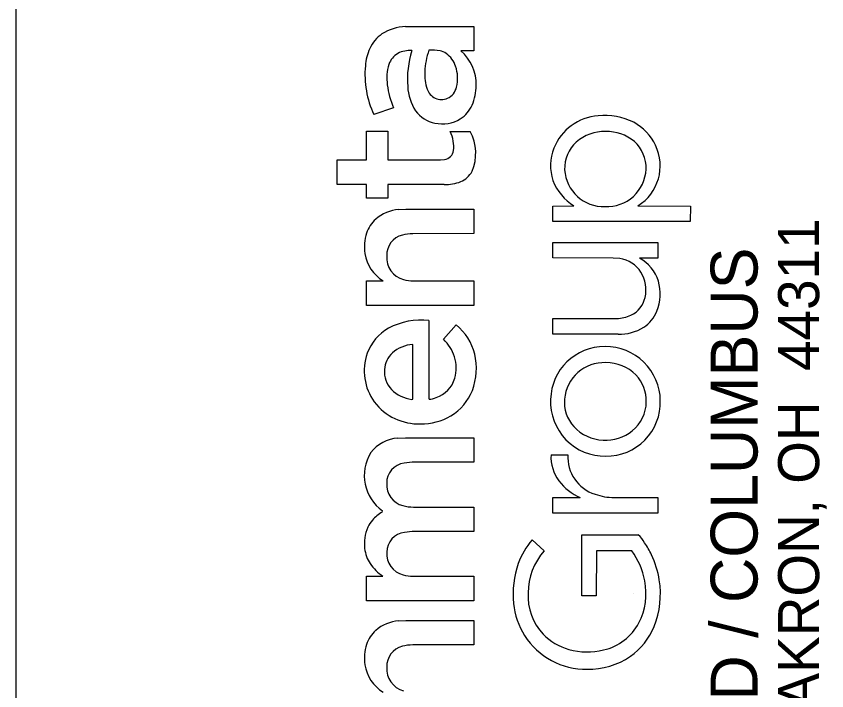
# Model space of a CAD drawing. Extents: x 0 to 34, y 0 to 22.
# Drawn here: x 32 to 32.984, y 3.382 to 4.202 of the extents above; entities that cross this region are included whole.
import ezdxf

# ---------------------------------------------------------------- set-up
doc = ezdxf.new("R2010")
doc.units = 0
doc.layers.add('SH_Border', color=7, linetype='Continuous')
doc.layers.add('SH_Data', color=7, linetype='Continuous')

msp = doc.modelspace()

# ---------------------------------------------------------------- linework, layer by layer
at = {"layer": 'SH_Border'}
msp.add_line((32, 0.5), (32, 21.5), dxfattribs=at)
at = {"layer": 'SH_Data'}
for p, q in [((32.47265, 4.18899), (32.55553, 4.18918)), ((32.55553, 4.18918), (32.55571, 4.15956)), ((32.55571, 4.15956), (32.53971, 4.15956)), ((32.45818, 4.09045), (32.43431, 4.08233)), ((32.42542, 4.02705), (32.42548, 4.06209)), ((32.42548, 4.06209), (32.45108, 4.06209)), ((32.45108, 4.06209), (32.45117, 4.02705)), ((32.52695, 4.06159), (32.5511, 4.06159)), ((32.38964, 4.02701), (32.42542, 4.02705)), ((32.38964, 3.99719), (32.38964, 4.02701)), ((32.45117, 4.02705), (32.51498, 4.02705)), ((32.51498, 4.02705), (32.52005, 4.02749)), ((32.42542, 3.99717), (32.38964, 3.99719)), ((32.42542, 3.98067), (32.42542, 3.99717)), ((32.51969, 3.99718), (32.45108, 3.99715)), ((32.45108, 3.99715), (32.45108, 3.98066)), ((32.45108, 3.98066), (32.42542, 3.98067)), ((32.46439, 3.96686), (32.47289, 3.96732)), ((32.47289, 3.96732), (32.55571, 3.96732)), ((32.55571, 3.96732), (32.55571, 3.93753)), ((32.65152, 3.97113), (32.67709, 3.97115)), ((32.65152, 3.95215), (32.65152, 3.97113)), ((32.75491, 3.97132), (32.81858, 3.97108)), ((32.81858, 3.97108), (32.81843, 3.95215)), ((32.81843, 3.95215), (32.65152, 3.95215)), ((32.55571, 3.93753), (32.4814, 3.93746)), ((32.65152, 3.90801), (32.65153, 3.92672)), ((32.65153, 3.92672), (32.7791, 3.92664)), ((32.7791, 3.92664), (32.77908, 3.90796)), ((32.7249, 3.90796), (32.65152, 3.90801)), ((32.7328, 3.90727), (32.7249, 3.90796)), ((32.77908, 3.90796), (32.75689, 3.90796)), ((32.42542, 3.88016), (32.44552, 3.88021)), ((32.42542, 3.85035), (32.42542, 3.88016)), ((32.48222, 3.88021), (32.55569, 3.88021)), ((32.55569, 3.88021), (32.55571, 3.85045)), ((32.55571, 3.85045), (32.42542, 3.85035)), ((32.50108, 3.83209), (32.50118, 3.73657)), ((32.65154, 3.83443), (32.72905, 3.8345)), ((32.65165, 3.81543), (32.65154, 3.83443)), ((32.51882, 3.80927), (32.53422, 3.82662)), ((32.73073, 3.81543), (32.65165, 3.81543)), ((32.48144, 3.73644), (32.48144, 3.80296)), ((32.48016, 3.73628), (32.48144, 3.73644)), ((32.46329, 3.68915), (32.47259, 3.68968)), ((32.47259, 3.68968), (32.55557, 3.68968)), ((32.55557, 3.68968), (32.55571, 3.65982)), ((32.64932, 3.66907), (32.66978, 3.66907)), ((32.48058, 3.65981), (32.47102, 3.65881)), ((32.55571, 3.65982), (32.48058, 3.65981)), ((32.65152, 3.61699), (32.68476, 3.617)), ((32.65152, 3.598), (32.65152, 3.61699)), ((32.72605, 3.61703), (32.7791, 3.61696)), ((32.7791, 3.61696), (32.77903, 3.598)), ((32.48218, 3.60553), (32.55571, 3.60548)), ((32.55571, 3.60548), (32.55571, 3.57568)), ((32.44443, 3.59922), (32.44455, 3.60072)), ((32.77903, 3.598), (32.65152, 3.598)), ((32.4809, 3.57567), (32.47143, 3.57474)), ((32.55571, 3.57568), (32.4809, 3.57567)), ((32.62636, 3.56548), (32.64114, 3.55241)), ((32.6868, 3.57185), (32.75516, 3.57192)), ((32.6868, 3.49778), (32.6868, 3.57185)), ((32.70448, 3.55241), (32.70432, 3.49775)), ((32.74737, 3.55227), (32.70448, 3.55241)), ((32.42542, 3.49152), (32.42545, 3.52138)), ((32.42545, 3.52138), (32.44515, 3.52138)), ((32.48206, 3.52138), (32.55571, 3.52136)), ((32.55571, 3.52136), (32.55571, 3.49156)), ((32.70432, 3.49775), (32.6868, 3.49778)), ((32.75, 3.5), (32.75, 3.5)), ((32.55571, 3.49156), (32.42542, 3.49152)), ((32.46439, 3.46736), (32.47289, 3.46783)), ((32.47289, 3.46783), (32.55571, 3.46783)), ((32.55571, 3.46783), (32.55571, 3.43804)), ((32.55571, 3.43804), (32.4814, 3.43796))]:
    msp.add_line(p, q, dxfattribs=at)
for points in [[(32.47265, 4.18899), (32.55553, 4.18918), (32.55571, 4.15956)], [(32.55571, 4.15956), (32.53971, 4.15956)], [(32.45818, 4.09045), (32.43431, 4.08233)], [(32.51969, 3.99718), (32.45108, 3.99715), (32.45108, 3.98066), (32.42542, 3.98067), (32.42542, 3.99717), (32.38964, 3.99719), (32.38964, 4.02701), (32.42542, 4.02705), (32.42548, 4.06209), (32.45108, 4.06209), (32.45117, 4.02705), (32.51498, 4.02705), (32.52005, 4.02749)], [(32.52695, 4.06159), (32.5511, 4.06159)], [(32.46439, 3.96686), (32.47289, 3.96732), (32.55571, 3.96732), (32.55571, 3.93753), (32.4814, 3.93746)], [(32.75491, 3.97132), (32.81858, 3.97108), (32.81843, 3.95215), (32.65152, 3.95215)], [(32.65152, 3.95215), (32.65152, 3.97113), (32.67709, 3.97115)], [(32.7328, 3.90727), (32.7249, 3.90796), (32.65152, 3.90801), (32.65153, 3.92672), (32.7791, 3.92664), (32.77908, 3.90796), (32.75689, 3.90796)], [(32.42542, 3.85035), (32.42542, 3.88016), (32.44552, 3.88021)], [(32.48222, 3.88021), (32.55569, 3.88021), (32.55571, 3.85045), (32.42542, 3.85035)], [(32.50108, 3.83209), (32.50118, 3.73657)], [(32.73073, 3.81543), (32.65165, 3.81543), (32.65154, 3.83443), (32.72905, 3.8345)], [(32.51882, 3.80927), (32.53422, 3.82662)], [(32.48016, 3.73628), (32.48144, 3.73644), (32.48144, 3.80296)], [(32.46329, 3.68915), (32.47259, 3.68968), (32.55557, 3.68968), (32.55571, 3.65982), (32.48058, 3.65981), (32.47102, 3.65881)], [(32.64932, 3.66907), (32.66978, 3.66907)], [(32.72605, 3.61703), (32.7791, 3.61696), (32.77903, 3.598), (32.65152, 3.598)], [(32.65152, 3.598), (32.65152, 3.61699), (32.68476, 3.617)], [(32.48218, 3.60553), (32.55571, 3.60548), (32.55571, 3.57568), (32.4809, 3.57567), (32.47143, 3.57474)], [(32.44443, 3.59922), (32.44455, 3.60072)], [(32.62636, 3.56548), (32.64114, 3.55241)], [(32.74737, 3.55227), (32.70448, 3.55241), (32.70432, 3.49775), (32.6868, 3.49778), (32.6868, 3.57185), (32.75516, 3.57192)], [(32.42542, 3.49152), (32.42545, 3.52138), (32.44515, 3.52138)], [(32.48206, 3.52138), (32.55571, 3.52136), (32.55571, 3.49156), (32.42542, 3.49152)], [(32.46439, 3.46736), (32.47289, 3.46783), (32.55571, 3.46783), (32.55571, 3.43804), (32.4814, 3.43796)]]:
    msp.add_lwpolyline(points, dxfattribs=at)
for centre, radius, start, end in [((32.47452, 4.13256), 0.05646, 91.89422, 122.63175), ((32.47452, 4.13256), 0.05646, 91.89422, 122.63175), ((32.46847, 4.14467), 0.04302, 124.53704, 155.65938), ((32.46847, 4.14467), 0.04302, 124.53704, 155.65938), ((32.48824, 4.13612), 0.06457, 155.9764, 175.31491), ((32.48824, 4.13612), 0.06457, 155.9764, 175.31491), ((32.47525, 4.1356), 0.024, 119.42515, 161.66285), ((32.47525, 4.1356), 0.024, 119.42515, 161.66285), ((32.47786, 4.12778), 0.03213, 85.38017, 116.62224), ((32.47786, 4.12778), 0.03213, 85.38017, 116.62224), ((32.58787, 4.12508), 0.1129, 162.08213, 184.52847), ((32.58787, 4.12508), 0.1129, 162.08213, 184.52847), ((32.58013, 4.13131), 0.08411, 159.83657, 178.03621), ((32.58013, 4.13131), 0.08411, 159.83657, 178.03621), ((32.50509, 4.10743), 0.05302, 79.66963, 94.23216), ((32.50509, 4.10743), 0.05302, 79.66963, 94.23216), ((32.50892, 4.13643), 0.02384, 56.89129, 76.21489), ((32.50892, 4.13643), 0.02384, 56.89129, 76.21489), ((32.5052, 4.13184), 0.02973, 17.59837, 55.72819), ((32.5052, 4.13184), 0.02973, 17.59837, 55.72819), ((32.50551, 4.11914), 0.05295, 358.07459, 49.76196), ((32.50551, 4.11914), 0.05295, 358.07459, 49.76196), ((32.53639, 4.13078), 0.113, 174.61011, 205.38987), ((32.53639, 4.13078), 0.113, 174.61011, 205.38987), ((32.50758, 4.12645), 0.05758, 163.13694, 188.16749), ((32.50758, 4.12645), 0.05758, 163.13694, 188.16749), ((32.54655, 4.1303), 0.05063, 175.59026, 199.88569), ((32.54655, 4.1303), 0.05063, 175.59026, 199.88569), ((32.4916, 4.1264), 0.04435, 345.94084, 18.99188), ((32.4916, 4.1264), 0.04435, 345.94084, 18.99188), ((32.54725, 4.12973), 0.09735, 186.75982, 203.79807), ((32.54725, 4.12973), 0.09735, 186.75982, 203.79807), ((32.53279, 4.11874), 0.05752, 182.56764, 213.71437), ((32.53279, 4.11874), 0.05752, 182.56764, 213.71437), ((32.51521, 4.11994), 0.01989, 295.28829, 347.46387), ((32.51521, 4.11994), 0.01989, 295.28829, 347.46387), ((32.50187, 4.11678), 0.05657, 336.01604, 0.59505), ((32.50187, 4.11678), 0.05657, 336.01604, 0.59505), ((32.51642, 4.11886), 0.01841, 198.28436, 293.30806), ((32.51642, 4.11886), 0.01841, 198.28436, 293.30806), ((32.51487, 4.10782), 0.03656, 215.06685, 259.81327), ((32.51487, 4.10782), 0.03656, 215.06685, 259.81327), ((32.51752, 4.10969), 0.03938, 303.44357, 336.18), ((32.51752, 4.10969), 0.03938, 303.44357, 336.18), ((32.51753, 4.1131), 0.04227, 257.52557, 300.88195), ((32.51753, 4.1131), 0.04227, 257.52557, 300.88195), ((32.71081, 4.01825), 0.06243, 93.98662, 158.31194), ((32.71081, 4.01825), 0.06243, 93.98662, 158.31194), ((32.71557, 4.0065), 0.07459, 62.68889, 97.01346), ((32.71557, 4.0065), 0.07459, 62.68889, 97.01346), ((32.72123, 4.01914), 0.06076, 25.06574, 61.96022), ((32.72123, 4.01914), 0.06076, 25.06574, 61.96022), ((32.48625, 4.04199), 0.04518, 10.15449, 25.72303), ((32.48625, 4.04199), 0.04518, 10.15449, 25.72303), ((32.50302, 4.03506), 0.05491, 336.58903, 28.89913), ((32.50302, 4.03506), 0.05491, 336.58903, 28.89913), ((32.71379, 4.01017), 0.05134, 87.89653, 131.18123), ((32.71379, 4.01017), 0.05134, 87.89653, 131.18123), ((32.7175, 4.01023), 0.05127, 49.90886, 92.03625), ((32.7175, 4.01023), 0.05127, 49.90886, 92.03625), ((32.49573, 4.04365), 0.03556, 351.91398, 10.20594), ((32.49573, 4.04365), 0.03556, 351.91398, 10.20594), ((32.7092, 4.01674), 0.04338, 132.32887, 182.09489), ((32.7092, 4.01674), 0.04338, 132.32887, 182.09489), ((32.72154, 4.01733), 0.04327, 358.04871, 47.94467), ((32.72154, 4.01733), 0.04327, 358.04871, 47.94467), ((32.7245, 4.02004), 0.05743, 301.97764, 25.64176), ((32.7245, 4.02004), 0.05743, 301.97764, 25.64176), ((32.51837, 4.04001), 0.01263, 277.61423, 353.79181), ((32.51837, 4.04001), 0.01263, 277.61423, 353.79181), ((32.70695, 4.02016), 0.05815, 158.65601, 198.17101), ((32.70695, 4.02016), 0.05815, 158.65601, 198.17101), ((32.71717, 4.01801), 0.04766, 267.31494, 357.4019), ((32.71717, 4.01801), 0.04766, 267.31494, 357.4019), ((32.52913, 4.02612), 0.02749, 292.68889, 332.05977), ((32.52913, 4.02612), 0.02749, 292.68889, 332.05977), ((32.71352, 4.01815), 0.04776, 183.59741, 271.7045), ((32.71352, 4.01815), 0.04776, 183.59741, 271.7045), ((32.52088, 4.04856), 0.05139, 268.67266, 291.52354), ((32.52088, 4.04856), 0.05139, 268.67266, 291.52354), ((32.7103, 4.02433), 0.0627, 200.83985, 238.01619), ((32.7103, 4.02433), 0.0627, 200.83985, 238.01619), ((32.46871, 3.91716), 0.04988, 94.97056, 130.22484), ((32.46871, 3.91716), 0.04988, 94.97056, 130.22484), ((32.46348, 3.92551), 0.04016, 132.22383, 161.68229), ((32.46348, 3.92551), 0.04016, 132.22383, 161.68229), ((32.47872, 3.92108), 0.05602, 162.27398, 187.79173), ((32.47872, 3.92108), 0.05602, 162.27398, 187.79173), ((32.48108, 3.89145), 0.04601, 89.60515, 105.33026), ((32.48108, 3.89145), 0.04601, 89.60515, 105.33026), ((32.47482, 3.91155), 0.02498, 103.68683, 182.21395), ((32.47482, 3.91155), 0.02498, 103.68683, 182.21395), ((32.47027, 3.9209), 0.04763, 188.96462, 238.69865), ((32.47027, 3.9209), 0.04763, 188.96462, 238.69865), ((32.47735, 3.90846), 0.02757, 175.58441, 255.13816), ((32.47735, 3.90846), 0.02757, 175.58441, 255.13816), ((32.72711, 3.86998), 0.03772, 33.50082, 81.32954), ((32.72711, 3.86998), 0.03772, 33.50082, 81.32954), ((32.73239, 3.86485), 0.04959, 17.62209, 60.38974), ((32.73239, 3.86485), 0.04959, 17.62209, 60.38974), ((32.72414, 3.8695), 0.04048, 346.56179, 31.75389), ((32.72414, 3.8695), 0.04048, 346.56179, 31.75389), ((32.48183, 3.92235), 0.04215, 254.08913, 270.52838), ((32.48183, 3.92235), 0.04215, 254.08913, 270.52838), ((32.72343, 3.86415), 0.05838, 339.16197, 15.61485), ((32.72343, 3.86415), 0.05838, 339.16197, 15.61485), ((32.73371, 3.86616), 0.03042, 294.63214, 348.48625), ((32.73371, 3.86616), 0.03042, 294.63214, 348.48625), ((32.72747, 3.88081), 0.04633, 271.95199, 294.08943), ((32.72747, 3.88081), 0.04633, 271.95199, 294.08943), ((32.739, 3.85901), 0.04201, 303.10391, 338.15613), ((32.739, 3.85901), 0.04201, 303.10391, 338.15613), ((32.49176, 3.74874), 0.08387, 83.62118, 118.28448), ((32.49176, 3.74874), 0.08387, 83.62118, 118.28448), ((32.47894, 3.77368), 0.05583, 118.82935, 160.62242), ((32.47894, 3.77368), 0.05583, 118.82935, 160.62242), ((32.49399, 3.7763), 0.06443, 13.53275, 51.36266), ((32.49399, 3.7763), 0.06443, 13.53275, 51.36266), ((32.7321, 3.87256), 0.05715, 268.62699, 301.47779), ((32.7321, 3.87256), 0.05715, 268.62699, 301.47779), ((32.48033, 3.77018), 0.05485, 19.0387, 45.44322), ((32.48033, 3.77018), 0.05485, 19.0387, 45.44322), ((32.4844, 3.76071), 0.04236, 94.01311, 130.88062), ((32.4844, 3.76071), 0.04236, 94.01311, 130.88062), ((32.71435, 3.73484), 0.06552, 89.48213, 178.77752), ((32.71435, 3.73484), 0.06552, 89.48213, 178.77752), ((32.71582, 3.73414), 0.06623, 0.42265, 90.7613), ((32.71582, 3.73414), 0.06623, 0.42265, 90.7613), ((32.48697, 3.77074), 0.06438, 160.52138, 215.78155), ((32.48697, 3.77074), 0.06438, 160.52138, 215.78155), ((32.47703, 3.7709), 0.02985, 132.98553, 177.1802), ((32.47703, 3.7709), 0.02985, 132.98553, 177.1802), ((32.48289, 3.77384), 0.0758, 339.35431, 13.37708), ((32.48289, 3.77384), 0.0758, 339.35431, 13.37708), ((32.48724, 3.77433), 0.04701, 344.60723, 17.00675), ((32.48724, 3.77433), 0.04701, 344.60723, 17.00675), ((32.71397, 3.73244), 0.04846, 87.68827, 175.01696), ((32.71397, 3.73244), 0.04846, 87.68827, 175.01696), ((32.71659, 3.73036), 0.05052, 44.91202, 90.75914), ((32.71659, 3.73036), 0.05052, 44.91202, 90.75914), ((32.47824, 3.76966), 0.03114, 175.00138, 223.2876), ((32.47824, 3.76966), 0.03114, 175.00138, 223.2876), ((32.49895, 3.77177), 0.03504, 288.01084, 343.55364), ((32.49895, 3.77177), 0.03504, 288.01084, 343.55364), ((32.71955, 3.73452), 0.04549, 358.32279, 43.83486), ((32.71955, 3.73452), 0.04549, 358.32279, 43.83486), ((32.48546, 3.77826), 0.04232, 225.06454, 262.79701), ((32.48546, 3.77826), 0.04232, 225.06454, 262.79701), ((32.49548, 3.76982), 0.0626, 300.94393, 338.73223), ((32.49548, 3.76982), 0.0626, 300.94393, 338.73223), ((32.48908, 3.77516), 0.06872, 217.74341, 271.65606), ((32.48908, 3.77516), 0.06872, 217.74341, 271.65606), ((32.50129, 3.75678), 0.02021, 269.70042, 294.87295), ((32.50129, 3.75678), 0.02021, 269.70042, 294.87295), ((32.71483, 3.7334), 0.06606, 177.53728, 270.94524), ((32.71483, 3.7334), 0.06606, 177.53728, 270.94524), ((32.71085, 3.73311), 0.0453, 175.51467, 221.42047), ((32.71085, 3.73311), 0.0453, 175.51467, 221.42047), ((32.71671, 3.73271), 0.06536, 269.30834, 1.67905), ((32.71671, 3.73271), 0.06536, 269.30834, 1.67905), ((32.71931, 3.73374), 0.04572, 308.90382, 359.30947), ((32.71931, 3.73374), 0.04572, 308.90382, 359.30947), ((32.49204, 3.77702), 0.07055, 269.20529, 300.33566), ((32.49204, 3.77702), 0.07055, 269.20529, 300.33566), ((32.71399, 3.73734), 0.05046, 222.66255, 268.37331), ((32.71399, 3.73734), 0.05046, 222.66255, 268.37331), ((32.71567, 3.73859), 0.05178, 266.55312, 308.67253), ((32.71567, 3.73859), 0.05178, 266.55312, 308.67253), ((32.46638, 3.64404), 0.04521, 93.91118, 142.30723), ((32.46638, 3.64404), 0.04521, 93.91118, 142.30723), ((32.47585, 3.64373), 0.05319, 148.28793, 233.9556), ((32.47585, 3.64373), 0.05319, 148.28793, 233.9556), ((32.69878, 3.66662), 0.04952, 177.16211, 216.28024), ((32.69878, 3.66662), 0.04952, 177.16211, 216.28024), ((32.71735, 3.66638), 0.04764, 176.76988, 252.15044), ((32.71735, 3.66638), 0.04764, 176.76988, 252.15044), ((32.47384, 3.63499), 0.02399, 96.75763, 181.6251), ((32.47384, 3.63499), 0.02399, 96.75763, 181.6251), ((32.47577, 3.63241), 0.02597, 175.81573, 256.16716), ((32.47577, 3.63241), 0.02597, 175.81573, 256.16716), ((32.70975, 3.67555), 0.06366, 216.91526, 246.88619), ((32.70975, 3.67555), 0.06366, 216.91526, 246.88619), ((32.7269, 3.69175), 0.07473, 251.13884, 269.34694), ((32.7269, 3.69175), 0.07473, 251.13884, 269.34694), ((32.4817, 3.65053), 0.04501, 254.34629, 270.61033), ((32.4817, 3.65053), 0.04501, 254.34629, 270.61033), ((32.4638, 3.56267), 0.04137, 117.91625, 139.24296), ((32.4638, 3.56267), 0.04137, 117.91625, 139.24296), ((32.46194, 3.56452), 0.03875, 139.52447, 154.84698), ((32.46194, 3.56452), 0.03875, 139.52447, 154.84698), ((32.47144, 3.5612), 0.04877, 156.06382, 187.3493), ((32.47144, 3.5612), 0.04877, 156.06382, 187.3493), ((32.47421, 3.55056), 0.02434, 96.5532, 179.94902), ((32.47421, 3.55056), 0.02434, 96.5532, 179.94902), ((32.70163, 3.50187), 0.09855, 139.79476, 159.13696), ((32.70163, 3.50187), 0.09855, 139.79476, 159.13696), ((32.72498, 3.53937), 0.04438, 30.98913, 47.16099), ((32.72498, 3.53937), 0.04438, 30.98913, 47.16099), ((32.46461, 3.55974), 0.04181, 186.5579, 213.38846), ((32.46461, 3.55974), 0.04181, 186.5579, 213.38846), ((32.67091, 3.50018), 0.11106, 25.30315, 33.96179), ((32.67091, 3.50018), 0.11106, 25.30315, 33.96179), ((32.47608, 3.54863), 0.02628, 175.722, 255.78627), ((32.47608, 3.54863), 0.02628, 175.722, 255.78627), ((32.69899, 3.50079), 0.07753, 138.25804, 179.70064), ((32.69899, 3.50079), 0.07753, 138.25804, 179.70064), ((32.67889, 3.50099), 0.08556, 10.07509, 36.83189), ((32.67889, 3.50099), 0.08556, 10.07509, 36.83189), ((32.6704, 3.49987), 0.11166, 8.80339, 25.33484), ((32.6704, 3.49987), 0.11166, 8.80339, 25.33484), ((32.47886, 3.57078), 0.0598, 214.70433, 235.68724), ((32.47886, 3.57078), 0.0598, 214.70433, 235.68724), ((32.7187, 3.49968), 0.11536, 161.14379, 185.62812), ((32.7187, 3.49968), 0.11536, 161.14379, 185.62812), ((32.48195, 3.56518), 0.0438, 253.66719, 270.14979), ((32.48195, 3.56518), 0.0438, 253.66719, 270.14979), ((32.68425, 3.50057), 0.08036, 333.46689, 11.03668), ((32.68425, 3.50057), 0.08036, 333.46689, 11.03668), ((32.67564, 3.49977), 0.10649, 338.28866, 9.28548), ((32.67564, 3.49977), 0.10649, 338.28866, 9.28548), ((32.68811, 3.49732), 0.06676, 176.66577, 223.6912), ((32.68811, 3.49732), 0.06676, 176.66577, 223.6912), ((32.69336, 3.49699), 0.08987, 185.50773, 212.01294), ((32.69336, 3.49699), 0.08987, 185.50773, 212.01294), ((32.46871, 3.41767), 0.04988, 94.97056, 130.22484), ((32.46871, 3.41767), 0.04988, 94.97056, 130.22484), ((32.69868, 3.49547), 0.0652, 282.88151, 331.81475), ((32.69868, 3.49547), 0.0652, 282.88151, 331.81475), ((32.46348, 3.42602), 0.04016, 132.22383, 161.68229), ((32.46348, 3.42602), 0.04016, 132.22383, 161.68229), ((32.69835, 3.49168), 0.08241, 305.03061, 337.67573), ((32.69835, 3.49168), 0.08241, 305.03061, 337.67573), ((32.69211, 3.49748), 0.08908, 212.70222, 270.71399), ((32.69211, 3.49748), 0.08908, 212.70222, 270.71399), ((32.69045, 3.50011), 0.07039, 224.02147, 253.88), ((32.69045, 3.50011), 0.07039, 224.02147, 253.88), ((32.47872, 3.42158), 0.05602, 162.27398, 187.79173), ((32.47872, 3.42158), 0.05602, 162.27398, 187.79173), ((32.47482, 3.41206), 0.02498, 103.68683, 182.21395), ((32.47482, 3.41206), 0.02498, 103.68683, 182.21395), ((32.48108, 3.39196), 0.04601, 89.60515, 105.33026), ((32.48108, 3.39196), 0.04601, 89.60515, 105.33026), ((32.69318, 3.51254), 0.08309, 254.45353, 283.9512), ((32.69318, 3.51254), 0.08309, 254.45353, 283.9512), ((32.69429, 3.49979), 0.09138, 269.3273, 304.19632), ((32.69429, 3.49979), 0.09138, 269.3273, 304.19632), ((32.47027, 3.42141), 0.04763, 188.96462, 238.69865), ((32.47027, 3.42141), 0.04763, 188.96462, 238.69865), ((32.47735, 3.40897), 0.02757, 175.58441, 255.13816), ((32.47735, 3.40897), 0.02757, 175.58441, 255.13816)]:
    msp.add_arc(centre, radius, start, end, dxfattribs=at)

# ---------------------------------------------------------------- texts
for s, height, p in [('450 GRANT ST., AKRON, OH  44311', 0.0498462, (32.97489, 2.83738)), ('AKRON / CLEVELAND / COLUMBUS', 0.056969, (32.90012, 2.638))]:
    msp.add_text(s, height=height, rotation=90, dxfattribs=at).set_placement(p)

doc.saveas('drawing.dxf')
